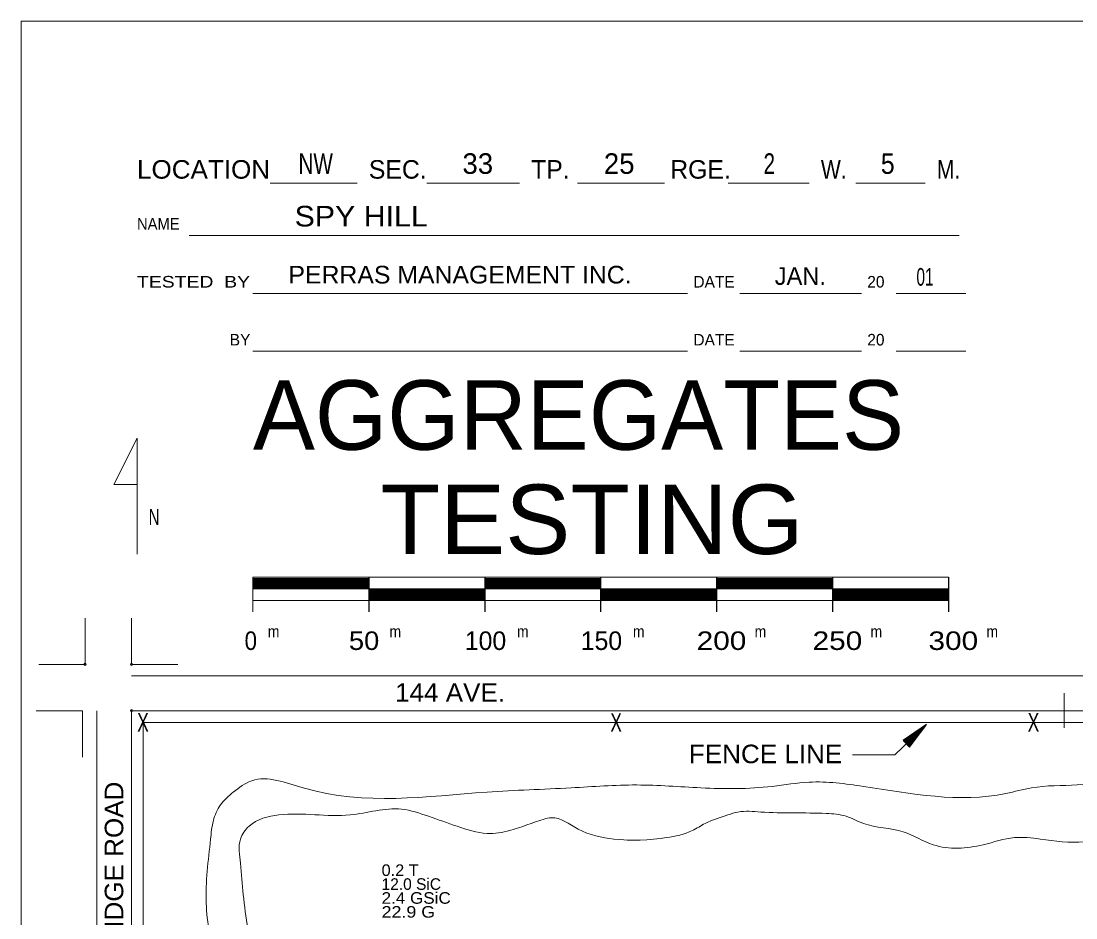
# Model space of a CAD drawing. Extents: x -496 to 480, y -450 to 700.
# Drawn here: x -450 to 5, y 312.9 to 700 of the extents above; entities that cross this region are included whole.
import ezdxf
from ezdxf.enums import TextEntityAlignment as Align

# ---------------------------------------------------------------- set-up
doc = ezdxf.new("R2010")
doc.units = 0
doc.header["$LTSCALE"] = 2
doc.header["$PDMODE"] = 32
doc.header["$PDSIZE"] = 1
for name, color, linetype, lineweight in [('1', 7, 'Continuous', 13), ('2', 7, 'Continuous', 35), ('3', 7, 'Continuous', 13), ('4', 7, 'Continuous', 25)]:
    doc.layers.add(name, color=color, linetype=linetype, lineweight=lineweight)

msp = doc.modelspace()

# ---------------------------------------------------------------- linework, layer by layer
at = {"layer": '1'}
for p, q in [((-342.517, 629.973), (-305.017, 629.973)), ((-275.017, 629.973), (-235.017, 629.973)), ((-210.017, 629.973), (-172.517, 629.973)), ((-145.017, 629.973), (-110.017, 629.973)), ((-90.017, 629.973), (-60.017, 629.973)), ((-377.517, 607.473), (-45.359, 607.473)), ((-350.017, 582.473), (-162.517, 582.473)), ((-140.017, 582.473), (-87.517, 582.473)), ((-72.517, 582.473), (-42.517, 582.473)), ((-350.017, 557.473), (-162.517, 557.473)), ((-140.017, 557.473), (-87.517, 557.473)), ((-72.517, 557.473), (-42.517, 557.473)), ((-350.017, 459.973), (-350.017, 444.973)), ((-50.017, 459.973), (-350.017, 459.973)), ((-350.017, 454.973), (-50.017, 454.973)), ((-422.391, 422.339), (-422.391, 442.339)), ((-402.391, 422.339), (-402.391, 442.339)), ((-422.391, 422.339), (-442.391, 422.339)), ((-0.017, 394.973), (-0.017, 409.973)), ((-423.537, 402.339), (-443.537, 402.339)), ((-423.537, 402.339), (-423.537, 382.339)), ((-402.391, 402.339), (-402.391, -402.333)), ((-382.391, 402.339), (-402.391, 402.339))]:
    msp.add_line(p, q, dxfattribs=at)
at = {"layer": '1', "lineweight": 25}
for p, q in [((-300.017, 459.973), (-300.017, 444.973)), ((-250.017, 459.973), (-250.017, 444.973)), ((-200.017, 459.973), (-200.017, 444.973)), ((-150.017, 459.973), (-150.017, 444.973)), ((-100.017, 459.973), (-100.017, 444.973)), ((-50.017, 459.973), (-50.017, 444.973)), ((-350.017, 459.473), (-300.017, 459.473)), ((-350.017, 458.973), (-300.017, 458.973)), ((-350.017, 458.473), (-300.017, 458.473)), ((-350.017, 457.973), (-300.017, 457.973)), ((-350.017, 457.473), (-300.017, 457.473)), ((-350.017, 456.973), (-300.017, 456.973)), ((-350.017, 456.473), (-300.017, 456.473)), ((-350.017, 456.473), (-300.017, 456.473)), ((-350.017, 456.473), (-300.017, 456.473)), ((-350.017, 455.973), (-300.017, 455.973)), ((-350.017, 455.973), (-300.017, 455.973)), ((-350.017, 455.473), (-300.017, 455.473)), ((-250.017, 459.473), (-200.017, 459.473)), ((-250.017, 458.973), (-200.017, 458.973)), ((-250.017, 458.473), (-200.017, 458.473)), ((-250.017, 457.973), (-200.017, 457.973)), ((-250.017, 457.473), (-200.017, 457.473)), ((-250.017, 456.973), (-200.017, 456.973)), ((-250.017, 456.473), (-200.017, 456.473)), ((-250.017, 455.973), (-200.017, 455.973)), ((-250.017, 455.473), (-200.017, 455.473)), ((-150.017, 459.473), (-100.017, 459.473)), ((-150.017, 458.973), (-100.017, 458.973)), ((-150.017, 458.473), (-100.017, 458.473)), ((-150.017, 457.973), (-100.017, 457.973)), ((-150.017, 457.473), (-100.017, 457.473)), ((-150.017, 456.973), (-100.017, 456.973)), ((-150.017, 456.473), (-100.017, 456.473)), ((-150.017, 455.973), (-100.017, 455.973)), ((-150.017, 455.473), (-100.017, 455.473)), ((-300.017, 454.473), (-250.017, 454.473)), ((-300.017, 453.973), (-250.017, 453.973)), ((-300.017, 453.473), (-250.017, 453.473)), ((-300.017, 452.973), (-250.017, 452.973)), ((-300.017, 452.473), (-250.017, 452.473)), ((-300.017, 451.973), (-250.017, 451.973)), ((-300.017, 451.473), (-250.017, 451.473)), ((-300.017, 450.973), (-250.017, 450.973)), ((-300.017, 450.473), (-250.017, 450.473)), ((-200.017, 454.473), (-150.017, 454.473)), ((-200.017, 453.973), (-150.017, 453.973)), ((-200.017, 453.473), (-150.017, 453.473)), ((-200.017, 452.973), (-150.017, 452.973)), ((-200.017, 452.473), (-150.017, 452.473)), ((-200.017, 451.973), (-150.017, 451.973)), ((-200.017, 451.473), (-150.017, 451.473)), ((-200.017, 450.973), (-150.017, 450.973)), ((-200.017, 450.473), (-150.017, 450.473)), ((-100.017, 454.473), (-50.017, 454.473)), ((-100.017, 453.973), (-50.017, 453.973)), ((-100.017, 453.473), (-50.017, 453.473)), ((-100.017, 452.973), (-50.017, 452.973)), ((-100.017, 452.473), (-50.017, 452.473)), ((-100.017, 451.973), (-50.017, 451.973)), ((-100.017, 451.473), (-50.017, 451.473)), ((-100.017, 450.973), (-50.017, 450.973)), ((-100.017, 450.473), (-50.017, 450.473))]:
    msp.add_line(p, q, dxfattribs=at)
at = {"layer": '1'}
for points in [[(449.983, -450.027), (449.983, 399.973), (449.983, 699.973), (-450.017, 699.973), (-450.017, 49.973), (-450.017, -450.027)], [(-400.017, 469.973), (-400.017, 519.973), (-410.017, 499.973), (-400.017, 499.973)], [(-350.017, 449.973), (-50.017, 449.973), (-50.017, 459.973)], [(-402.391, 422.339), (-382.391, 422.339), (-402.391, 422.339)], [(402.281, -402.333), (402.281, 402.339), (-402.391, 402.339)]]:
    msp.add_lwpolyline(points, dxfattribs=at)
for p in [(-422.391, 422.339), (-402.391, 422.339), (-402.391, 402.339)]:
    msp.add_point(p, dxfattribs=at)
at = {"layer": '3'}
for p, q in [((402.281, 417.339), (-402.391, 417.339)), ((-417.391, 402.339), (-417.391, -402.333))]:
    msp.add_line(p, q, dxfattribs=at)
msp.add_lwpolyline([(410.562, 397.339), (-397.391, 397.339), (-397.391, 23.005)], dxfattribs=at)
for points in [[(-360.928, 32.503), (-364.618, 32.503), (-370.152, 36.803), (-366.462, 52.771), (-367.077, 89.622), (-367.692, 111.733), (-367.692, 129.544), (-365.233, 204.474), (-367.692, 222.9), (-367.692, 241.939), (-367.692, 275.719), (-367.692, 294.145), (-370.152, 319.326), (-368.307, 346.964), (-367.077, 354.949), (-364.003, 361.705), (-358.469, 367.232), (-350.475, 372.146), (-328.339, 369.075), (-249.018, 367.232), (-212.739, 369.075), (-184.454, 370.303), (-156.784, 369.075), (-126.039, 369.689), (-110.052, 371.532), (-86.686, 369.689), (-25.196, 366.618), (-14.128, 369.075), (5.548, 370.303), (27.07, 370.918), (45.517, 368.461), (60.889, 369.075)], [(-360.928, 32.503), (-354.165, 42.33), (-351.09, 51.543), (-352.935, 81.024), (-355.394, 107.433), (-352.32, 127.087), (-351.09, 165.167), (-353.55, 187.891), (-353.55, 218.6), (-356.009, 235.798), (-352.32, 258.522), (-350.475, 281.861), (-352.32, 308.271), (-354.165, 323.011), (-355.394, 336.523), (-355.394, 346.964), (-351.705, 352.492), (-338.792, 357.406), (-308.048, 357.406), (-285.911, 359.862), (-274.228, 356.791), (-261.93, 352.492), (-249.018, 349.421), (-239.179, 350.65), (-224.422, 355.563), (-221.347, 356.177), (-209.664, 351.264), (-194.292, 346.964), (-171.541, 347.579), (-160.473, 350.65), (-154.939, 353.72), (-145.101, 357.406), (-140.796, 358.634), (-130.958, 358.634), (-102.673, 358.02), (-94.064, 356.791), (-86.686, 353.72), (-69.469, 350.035), (-56.556, 344.508), (-35.035, 344.508), (-21.507, 347.579), (-10.439, 346.964), (8.623, 345.736), (21.536, 349.421), (27.07, 352.492), (41.212, 356.177), (52.895, 357.406)]]:
    msp.add_spline(points, degree=3, dxfattribs=at)
at = {"layer": '4', "lineweight": 13}
msp.add_lwpolyline([(-91.399, 383.307), (-73.191, 383.307), (-59.449, 396.347)], dxfattribs=at)
at = {"layer": '4'}
msp.add_lwpolyline([(-59.449, 396.347), (-69.53, 389.538), (-66.777, 386.636)], close=True, dxfattribs=at)
msp.add_lwpolyline([(-69.378, 389.519), (-59.866, 395.952), (-66.772, 386.867), (-69.226, 389.423), (-60.4, 395.445), (-66.749, 387.125), (-68.999, 389.432), (-60.965, 394.91), (-66.758, 387.417), (-68.756, 389.365), (-61.621, 394.316), (-66.719, 387.723), (-68.448, 389.357), (-62.406, 393.603), (-66.756, 388.045), (-68.113, 389.317), (-63.251, 392.83), (-66.776, 388.473), (-67.763, 389.325), (-64.206, 392.013), (-66.704, 388.899), (-67.349, 389.36), (-65.274, 390.971), (-66.674, 389.432)], dxfattribs=at)

# ---------------------------------------------------------------- texts
at = {"layer": '1'}
for s, height, width, p in [('NW', 8.89, 0.75, (-322.943, 634.038)), ('2', 8.89, 0.75, (-127.28, 634.037)), ('5', 8.89, 0.9, (-76.181, 634.038)), ('SPY HILL', 8.89, 1.1, (-303.323, 611.329)), ('PERRAS MANAGEMENT INC.', 7.62, 1.05, (-260.682, 586.728)), ('01', 7.62, 0.65, (-60.119, 585.781))]:
    msp.add_text(s, height=height, dxfattribs=dict(at, width=width)).set_placement(p, align=Align.CENTER)
for s, height, p in [('33', 8.89, (-253.021, 634.038)), ('25', 8.89, (-192.027, 634.038)), ('JAN.', 7.62, (-113.875, 586.148))]:
    msp.add_text(s, height=height, dxfattribs=at).set_placement(p, align=Align.CENTER)
for s, height, width, p in [('LOCATION', 8, 1.05, (-400.017, 631.973)), ('W.', 8, 0.85, (-105.017, 631.973)), ('M.', 8, 0.85, (-55.017, 631.973)), ('NAME', 5, 0.95, (-400.017, 609.973)), ('TESTED  BY', 5, 1.25, (-400.017, 584.973)), ('TESTING', 30, 1.05, (-295.017, 469.973)), ('N', 7, 0.7, (-395.017, 482.473)), ('m', 5, 0.9, (-343.607, 434.073)), ('m', 5, 0.9, (-291.107, 434.073)), ('m', 5, 0.9, (-236.107, 434.073)), ('m', 5, 0.9, (-186.107, 434.073)), ('m', 5, 0.9, (-133.607, 434.073)), ('m', 5, 0.9, (-83.607, 434.073)), ('m', 5, 0.9, (-33.607, 434.073)), ('0', 8, 0.9, (-353.607, 428.573)), ('50', 8, 1.1, (-308.607, 428.573)), ('200', 8, 1.2, (-158.607, 428.573)), ('250', 8, 1.2, (-108.607, 428.573)), ('300', 8, 1.2, (-58.607, 428.573))]:
    msp.add_text(s, height=height, dxfattribs=dict(at, width=width)).set_placement(p)
for s, height, p in [('SEC.', 8, (-300.017, 631.973)), ('TP.', 8, (-230.017, 631.973)), ('RGE.', 8, (-170.017, 631.973)), ('DATE', 5, (-160.017, 584.973)), ('20', 5, (-85.017, 584.973)), ('BY', 5, (-360.017, 559.973)), ('DATE', 5, (-160.017, 559.973)), ('20', 5, (-85.017, 559.973)), ('AGGREGATES', 30, (-350.017, 514.973)), ('100', 8, (-258.607, 428.573)), ('150', 8, (-208.607, 428.573))]:
    msp.add_text(s, height=height, dxfattribs=at).set_placement(p)
at = {"layer": '2'}
for s, width, p in [('0.2 T      ', 1.05, (-294.511, 331.044)), ('2.4 GSiC   ', 1.1, (-294.511, 319.044)), ('22.9 G     ', 1.15, (-294.511, 313.044))]:
    msp.add_text(s, height=5, dxfattribs=dict(at, width=width)).set_placement(p)
msp.add_text('12.0 SiC   ', height=5, dxfattribs=at).set_placement((-294.511, 325.044))
at = {"layer": '3', "width": 0.7}
for p in [(-397.443, 393.299), (-193.353, 393.248), (-13.325, 393.325)]:
    msp.add_text('X', height=8, dxfattribs=at).set_placement(p, align=Align.CENTER)
at = {"layer": '4', "width": 1.05}
for s, p in [('144 AVE.', (-264.988, 406.19)), ('FENCE LINE', (-128.874, 379.706))]:
    msp.add_text(s, height=8, dxfattribs=at).set_placement(p, align=Align.CENTER)
msp.add_text('ROCKY RIDGE ROAD', height=8, rotation=90, dxfattribs=at).set_placement((-405.943, 314.64), align=Align.CENTER)

doc.saveas('drawing.dxf')
